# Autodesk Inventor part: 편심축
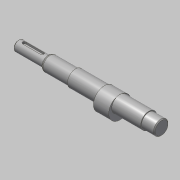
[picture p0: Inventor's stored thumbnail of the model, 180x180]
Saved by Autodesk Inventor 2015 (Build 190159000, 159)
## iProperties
Created: 2017-08
Part Number: 편심축
Material: 강철, 연강
Document SubType Name: Modeling
Designer: mduedu
Density: 7.86 g/cm^3
Appearance: 강철
Mass: 338.399 g
Surface Area: 105.4 cm^2
Volume: 43.0533 cm^3
Author: mduedu
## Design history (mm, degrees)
sketch "스케치1"
  geometry: L1 (0, 0)-(168, 0); L2 (168, 0)-(168, 8.5); L3 (168, 8.5)-(153, 8.5); L4 (153, 8.5)-(153, 9.5); L5 (153, 9.5)-(67, 9.5); L6 (67, 9.5)-(67, 8.5); L7 (67, 8.5)-(35, 8.5); L8 (35, 8.5)-(35, 6); L9 (35, 6)-(0, 6); L10 (0, 6)-(0, 0)
  constraints: 20 end point, 6 parallel, 2 collinear, 2 perpendicular, 1 horizontal
  dimensions: "d0" = 168 distance of L1.start L1.end; "d1" = 17 diameter of L3 L1; "d2" = 19 diameter of L5 L1; "d3" = 12 diameter of L9 L1; "d4" = 35 distance of L8.end L9.end; "d5" = 15 distance of L2.end L3.end; "d6" = 86 distance of L4.end L5.end
revolve "회전1" sketch "스케치1" stored, may be unused: angle "d7" = 90 deg
node "작업 평면1"
sketch "스케치2"
  geometry: C1 r 9.5 at (0, 0) reference; C2 r 13 at (0, -3.5); 1 further point
  constraints: 1 centre point, 1 tangent, 1 vertical alignment
  dimensions: "d8" = 3.5 distance of point (0, 0) C2.centre
extrude "돌출1" join sketch "스케치2" stored distance "d9" = 18; taper "d10" = 0 deg
chamfer "모따기1" distance "d11" = 1; stored, may be unused: second distance "d12" = 2, angle "d13" = 45 deg
node "작업 평면2"
sketch "스케치3"
  geometry: L1 (10.5, -2)-(-10.5, -2); L2 (-10.5, -2)-(-10.5, 2); L3 (-10.5, 2)-(10.5, 2); L4 (10.5, 2)-(10.5, -2); L5 (17.5, 6)-(17.5, -6) reference; L6 (-17.5, 8.5)-(-17.5, -8.5) reference; A1 r 2 centre (10.5, 0) between (10.5, -2) and (10.5, 2); A2 r 2 centre (-10.5, 0) between (-10.5, 2) and (-10.5, -2); A3 r 2 centre (10.5, 0) between (10.5, 2) and (10.5, -2); A4 r 2 centre (-10.5, 0) between (-10.5, -2) and (-10.5, 2); 1 further point
  constraints: 8 end point, 8 point on circle, 4 centre point, 2 midpoint, 2 parallel, 1 horizontal, 1 horizontal alignment, 1 perpendicular
  dimensions: "d14" = 25 dimension on A2 A1; "d16" = 4 distance between parallel lines of L3 L1; "d17" = 5 distance edge to line of A1 L5; "d46" = 5 distance edge to line of A2 L6 (derived)
extrude "돌출2" cut sketch "스케치3" distance "d18" = 2.5; taper "d19" = 0 deg
chamfer "모따기2" distance "d20" = 1; stored, may be unused: second distance "d21" = 2, angle "d22" = 45 deg
chamfer "모따기4" distance "d39" = 1.82; stored, may be unused: second distance "d40" = 2, angle "d41" = 30 deg
fillet "모깎기4" dims "d45" = 2
hole "구멍1" diameter "d29" = 3.242; stored, may be unused: countersink angle "d33" = 90 deg, drill point angle "d35" = 118 deg; dims "d30" = 8, "d31" = 4, "d32" = 2, "d34" = 10, "d36" = 10, "d37" = 10
node "솔리드1"
node "절단 모서리 투영1"
